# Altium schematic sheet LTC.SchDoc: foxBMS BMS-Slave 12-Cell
size A3; DocumentNumber: 2; SheetNumber: 2; SheetTotal: 15; AUTHOR: Fraunhofer IISB foxBMS Team; SheetDescription: Primary LTC6813
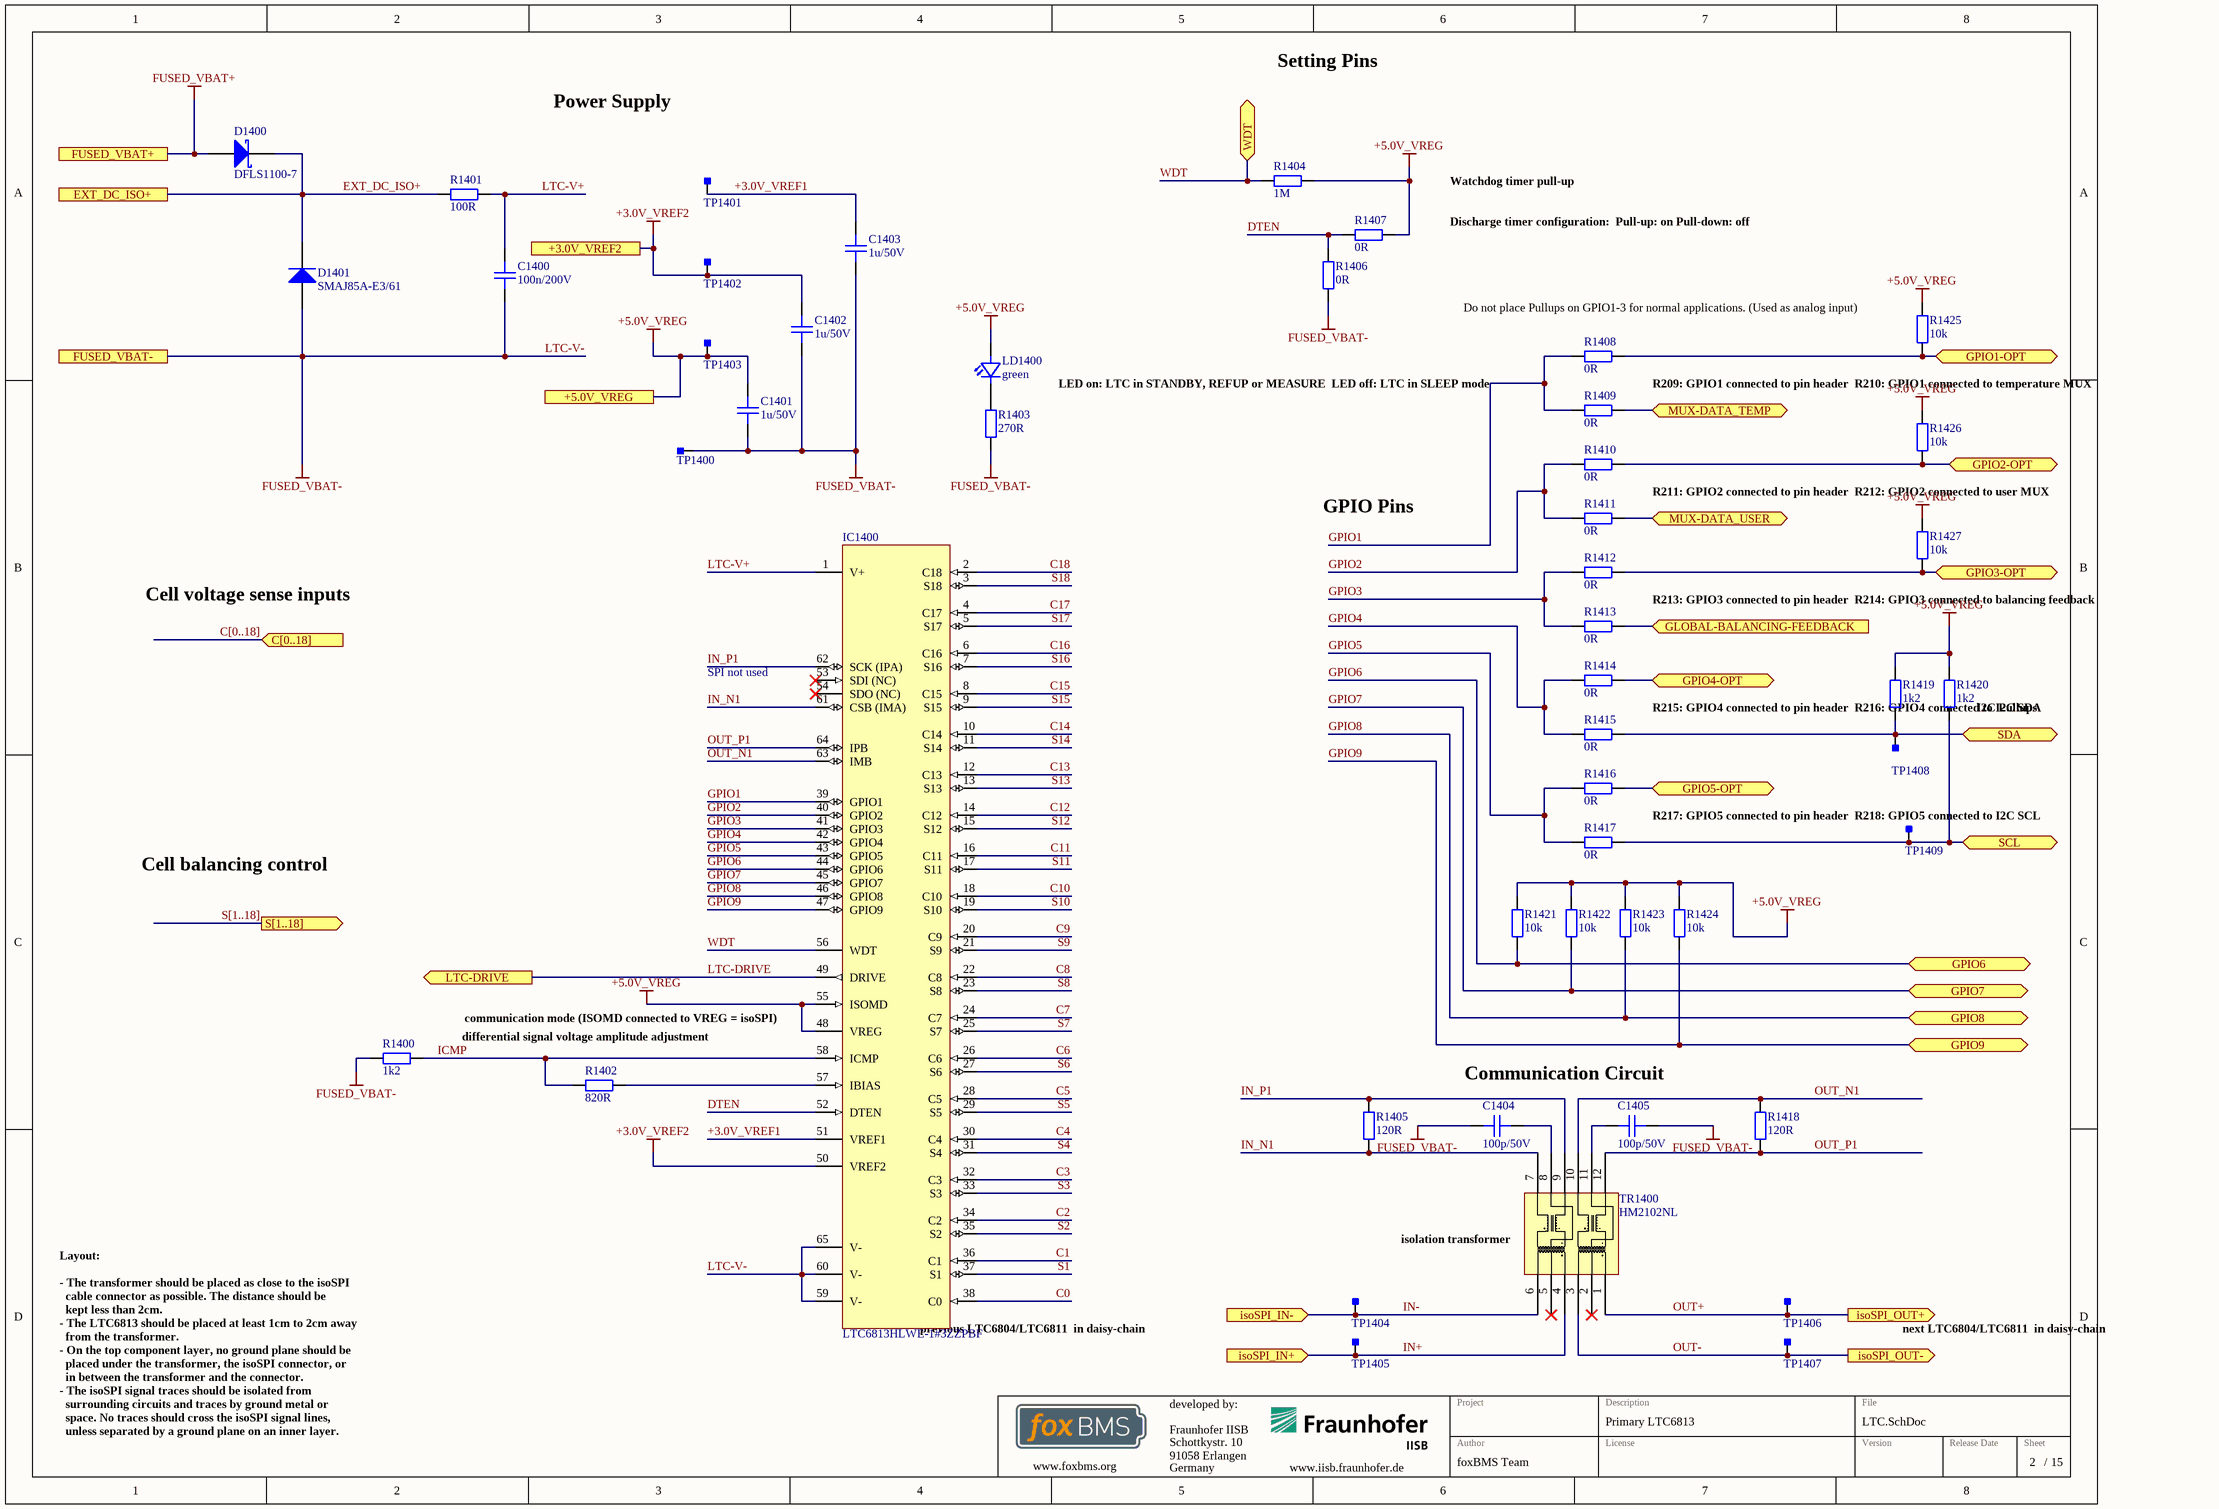
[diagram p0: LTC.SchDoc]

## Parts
C1400  100n/200V  [CAPC3216X18N]
C1401  1u/50V  [CAPC2012X14N]
C1402  1u/50V  [CAPC2012X14N]
C1403  1u/50V  [CAPC2012X14N]
C1404  100p/50V  [CAPC1608X08N]
C1405  100p/50V  [CAPC1608X08N]
D1400  DFLS1100-7  [DIOD-POWERDI123-2_V]
D1401  SMAJ85A-E3/61  [VISH-DO-214AC-2_L]
IC1400  LTC6813HLWE-1#3ZZPBF  [TSQFP50P1200X1200X160_HS-65N]
LD1400  green  [LEDC1608X07N]
R1400  1k2  [RESC1608X05N]
R1401  100R  [RESC2012X05N]
R1402  820R  [RESC1608X05N]
R1403  270R  [RESC1608X05N]
R1404  1M  [RESC1608X05N]
R1405  120R  [RESC1608X05N]
R1406  0R  [RESC1608X05N]
R1407  0R  [RESC1608X05N]
R1408  0R  [RESC1608X05N]
R1409  0R  [RESC1608X05N]
R1410  0R  [RESC1608X05N]
R1411  0R  [RESC1608X05N]
R1412  0R  [RESC1608X05N]
R1413  0R  [RESC1608X05N]
R1414  0R  [RESC1608X05N]
R1415  0R  [RESC1608X05N]
R1416  0R  [RESC1608X05N]
R1417  0R  [RESC1608X05N]
R1418  120R  [RESC1608X05N]
R1419  1k2  [RESC1608X05N]
R1420  1k2  [RESC1608X05N]
R1421  10k  [RESC1608X05N]
R1422  10k  [RESC1608X05N]
R1423  10k  [RESC1608X05N]
R1424  10k  [RESC1608X05N]
R1425  10k  [RESC1608X05N]
R1426  10k  [RESC1608X05N]
R1427  10k  [RESC1608X05N]
TP1400  Testpoint_Square  [Testpoint_S1]  (value not drawn)  (no BOM)
TP1401  Testpoint_Square  [Testpoint_S1]  (value not drawn)  (no BOM)
TP1402  Testpoint_Square  [Testpoint_S1]  (value not drawn)  (no BOM)
TP1403  Testpoint_Square  [Testpoint_S1]  (value not drawn)  (no BOM)
TP1404  Testpoint_Square  [Testpoint_S1]  (value not drawn)  (no BOM)
TP1405  Testpoint_Square  [Testpoint_S1]  (value not drawn)  (no BOM)
TP1406  Testpoint_Square  [Testpoint_S1]  (value not drawn)  (no BOM)
TP1407  Testpoint_Square  [Testpoint_S1]  (value not drawn)  (no BOM)
TP1408  Testpoint_Square  [Testpoint_S1]  (value not drawn)  (no BOM)
TP1409  Testpoint_Square  [Testpoint_S1]  (value not drawn)  (no BOM)
TR1400  HM2102NL  [HM2102NL]

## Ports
+3.0V_VREF2, +5.0V_VREG, C[0..18] (in), EXT_DC_ISO+, FUSED_VBAT+, FUSED_VBAT-, GLOBAL-BALANCING-FEEDBACK (in), GPIO1-OPT (bidir), GPIO2-OPT (bidir), GPIO3-OPT (bidir), GPIO4-OPT (bidir), GPIO5-OPT (bidir), GPIO6 (bidir), GPIO7 (bidir), GPIO8 (bidir), GPIO9 (bidir), isoSPI_IN+ (in), isoSPI_IN- (in), isoSPI_OUT+ (out), isoSPI_OUT- (out), LTC-DRIVE (out), MUX-DATA_TEMP (bidir), MUX-DATA_USER (bidir), S[1..18] (out), SCL (bidir), SDA (bidir), WDT (bidir)

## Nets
+3.0V_VREF2: C1402.2 IC1400.50(VREF2) TP1402.1 ; port +3.0V_VREF2
+5.0V_VREG: C1401.2 IC1400.48(VREG) IC1400.55(ISOMD) LD1400.2(A) R1404.2 R1407.2 R1419.2 R1420.2 R1421.2 R1422.2 R1423.2 R1424.2 R1425.2 R1426.2 R1427.2 TP1403.1 ; port +5.0V_VREG
FUSED_VBAT+: D1400.1(A) ; port FUSED_VBAT+
LTC-V-: C1400.2 C1401.1 C1402.1 C1403.1 C1404.1 C1405.1 D1401.2(A) IC1400.59(V-) IC1400.60(V-) IC1400.65(V-) R1400.1 R1403.1 R1406.1 TP1400.1 ; port FUSED_VBAT-  [also labelled FUSED_VBAT-]
+3.0V_VREF1: C1403.2 IC1400.51(VREF1) TP1401.1
C0: IC1400.38(C0)
C1: IC1400.36(C1)
C2: IC1400.34(C2)
C3: IC1400.32(C3)
C4: IC1400.30(C4)
C5: IC1400.28(C5)
C6: IC1400.26(C6)
C7: IC1400.24(C7)
C8: IC1400.22(C8)
C9: IC1400.20(C9)
C10: IC1400.18(C10)
C11: IC1400.16(C11)
C12: IC1400.14(C12)
C13: IC1400.12(C13)
C14: IC1400.10(C14)
C15: IC1400.8(C15)
C16: IC1400.6(C16)
C17: IC1400.4(C17)
C18: IC1400.2(C18)
DTEN: IC1400.52(DTEN) R1406.2 R1407.1
EXT_DC_ISO+: D1400.2(K) D1401.1(K) R1401.1 ; port EXT_DC_ISO+
GLOBAL-BALANCING-FEEDBACK: R1413.1 ; port GLOBAL-BALANCING-FEEDBACK
GPIO1: IC1400.39(GPIO1) R1408.2 R1409.2
GPIO1-OPT: R1408.1 R1425.1 ; port GPIO1-OPT
GPIO2: IC1400.40(GPIO2) R1410.2 R1411.2
GPIO2-OPT: R1410.1 R1426.1 ; port GPIO2-OPT
GPIO3: IC1400.41(GPIO3) R1412.2 R1413.2
GPIO3-OPT: R1412.1 R1427.1 ; port GPIO3-OPT
GPIO4: IC1400.42(GPIO4) R1414.2 R1415.2
GPIO4-OPT: R1414.1 ; port GPIO4-OPT
GPIO5: IC1400.43(GPIO5) R1416.2 R1417.2
GPIO5-OPT: R1416.1 ; port GPIO5-OPT
GPIO6: IC1400.44(GPIO6) R1421.1 ; port GPIO6
GPIO7: IC1400.45(GPIO7) R1422.1 ; port GPIO7
GPIO8: IC1400.46(GPIO8) R1423.1 ; port GPIO8
GPIO9: IC1400.47(GPIO9) R1424.1 ; port GPIO9
ICMP: IC1400.58(ICMP) R1400.2 R1402.1
IN+: TP1405.1 TR1400.4 ; port isoSPI_IN+
IN-: TP1404.1 TR1400.6 ; port isoSPI_IN-
IN_N1: IC1400.61(CSB_(IMA)) R1405.2 TR1400.7
IN_P1: IC1400.62(SCK_(IPA)) R1405.1 TR1400.9
LTC-DRIVE: IC1400.49(DRIVE) ; port LTC-DRIVE
LTC-V+: C1400.1 IC1400.1(V+) R1401.2
MUX-DATA_TEMP: R1409.1 ; port MUX-DATA_TEMP
MUX-DATA_USER: R1411.1 ; port MUX-DATA_USER
OUT+: TP1406.1 TR1400.1 ; port isoSPI_OUT+
OUT-: TP1407.1 TR1400.3 ; port isoSPI_OUT-
OUT_N1: IC1400.63(IMB) R1418.2 TR1400.10
OUT_P1: IC1400.64(IPB) R1418.1 TR1400.12
S1: IC1400.37(S1)
S2: IC1400.35(S2)
S3: IC1400.33(S3)
S4: IC1400.31(S4)
S5: IC1400.29(S5)
S6: IC1400.27(S6)
S7: IC1400.25(S7)
S8: IC1400.23(S8)
S9: IC1400.21(S9)
S10: IC1400.19(S10)
S11: IC1400.17(S11)
S12: IC1400.15(S12)
S13: IC1400.13(S13)
S14: IC1400.11(S14)
S15: IC1400.9(S15)
S16: IC1400.7(S16)
S17: IC1400.5(S17)
S18: IC1400.3(S18)
SCL: R1417.1 R1420.1 TP1409.1 ; port SCL
SDA: R1415.1 R1419.1 TP1408.1 ; port SDA
WDT: IC1400.56(WDT) R1404.1 ; port WDT
NetC1404_2: C1404.2 TR1400.8
NetC1405_2: C1405.2 TR1400.11
NetIC1400_57: IC1400.57(IBIAS) R1402.2
NetLD1400_1: LD1400.1(C) R1403.2

Not connected (* = marked no-connect by the designer): IC1400 53(SDI_(NC))* 54(SDO_(NC))*; TR1400 2* 5*

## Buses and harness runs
bus C[0..18] = port C[0..18]
bus S[1..18] = port S[1..18]

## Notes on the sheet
- Power Supply
- Setting Pins
- Watchdog timer pull-up
- Discharge timer configuration:
  Pull-up: on
  Pull-down: off
- (near R1425) Do not place Pullups on GPIO1-3 for normal applications. (Used as analog input)
- LED on: LTC in STANDBY, REFUP or MEASURE
  LED off: LTC in SLEEP mode
- R209: GPIO1 connected to pin header
  R210: GPIO1 connected to temperature MUX
- GPIO Pins
- R211: GPIO2 connected to pin header
  R212: GPIO2 connected to user MUX
- Cell voltage sense inputs
- R213: GPIO3 connected to pin header
  R214: GPIO3 connected to balancing feedback
- SPI not used
- R215: GPIO4 connected to pin header
  R216: GPIO4 connected to I2C SDA
- (near R1420) I2C Pullups
- (near TP1409) R217: GPIO5 connected to pin header
  R218: GPIO5 connected to I2C SCL
- Cell balancing control
- communication mode (ISOMD connected to VREG = isoSPI)
- differential signal voltage amplitude adjustment
- Communication Circuit
- (near TR1400) isolation transformer
- (near TP1405) previous LTC6804/LTC6811
  in daisy-chain
- next LTC6804/LTC6811
  in daisy-chain
- Layout:
  - The transformer should be placed as close to the isoSPI
  cable connector as possible. The distance should be
  kept less than 2cm.
  - The LTC6813 should be placed at least 1cm to 2cm away
  from the transformer.
  - On the top component layer, no ground plane should be
  placed under the transformer, the isoSPI connector, or
  in between the transformer and the connector.
  - The isoSPI signal traces should be isolated from
  surrounding circuits and traces by ground metal or
  space. No traces should cross the isoSPI signal lines,
  unless separated by a ground plane on an inner layer.

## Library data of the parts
C1400 = gen_C_ceramic_100n_200V_X7R_1206: MLCC; Capacitance: 100n; Rated Voltage: 200V; Dielectric: X7R; Case EIA: 1206; Case Metric: 3216; Automotive Qualified: True
C1401-C1403 = gen_C_ceramic_1u_50V_X7R_0805: MLCC; Capacitance: 1u; Rated Voltage: 50V; Dielectric: X7R; Case EIA: 0805; Case Metric: 2012; Automotive Qualified: True; Tolerance: ± 10%; AVT Set: x
C1404 C1405 = gen_C_ceramic_100p_50V_C0G_0603: MLCC; Capacitance: 100p; Rated Voltage: 50V; Dielectric: C0G; Case EIA: 0603; Case Metric: 1608; Automotive Qualified: True; Tolerance: ± 10%
D1400 = CMP-2000-05099-1: 1 A High Voltage Schottky Barrier Rectifier, 0.62 V, -55 to 175 degC, 2- Pin POWERDI123, Pb-Free, Tape and Reel; Manufacturer: Diodes Inc; Average Rectified Current-Max: 1A; Peak Current-Max: 40A; Forward Voltage: 0.77V; Reverse Current-Max: 1µA; Reverse Voltage-Max [Vrrm]: 100V
D1401 = CMP-0548-00243-2: Transient Voltage Suppressor, 6.40 to 231 V, 85 V Stand-off Voltage, Uni-Directional, -55 to 155 degC, 2-pin DO-214AC, Pb-Free, Tape and Reel; Manufacturer: Vishay Semiconductor; VWM (V): 85; PPPM (W): 400, 300; VBR Uni-Directional (V): 6.4 to 231; IFSM: 40 A; ID (uA): 1
IC1400 = LTC6813HLWE-1#3ZZPBF: 18 Cell Multicell Battery Monitor, -40 to 125 degC, Pb-Free; PartNumber: LTC6811HG-1#PBF; Manufacturer: Linear Technology; Type of Charger: Battery Stack Monitor; Vin Max(V): 60; Battery Chemistry: Li-Ion, Li-Polymer, NiMH; Number of Cells: > 1000 V of stacked Li-Ion cells; Automotive Qualified: True; PnP Package: QFP-64
LD1400 = LED_0603_green_AECQ: TLMG1100-GS08; Manufacturer: Vishay; Breakdown Voltage: 5V; Continuous Forward Current: 20mA; Forward Voltage @ 20mA: 2.1V; Automotive Qualified: True
R1400 R1419 R1420 = gen_R_1k2_0603: SMD Resistor 1k2 0603; Tolerance: 1%; Power: 0.1W; Case EIA: 0603; Case Metric: 1608; Maximum Working Voltage: 75V; PnP Package: R_0603; Automotive Qualified: True
R1401 = gen_R_100R_0805: SMD Resistor 100R 0805; Tolerance: 1%; Power: 0.125W; Case EIA: 0805; Case Metric: 2012; Maximum Working Voltage: 150V; PnP Package: R_0805; Automotive Qualified: True
R1402 = gen_R_820R_0603: SMD Resistor 820R 0603; Tolerance: 1%; Power: 0.1W; Case EIA: 0603; Case Metric: 1608; Maximum Working Voltage: 75V; PnP Package: R_0603; Automotive Qualified: True
R1403 = gen_R_270R_0603: SMD Resistor 270R 0603; Tolerance: 1%; Power: 0.1W; Case EIA: 0603; Case Metric: 1608; Maximum Working Voltage: 75V; PnP Package: R_0603; Automotive Qualified: True
R1404 = gen_R_1M_0603: SMD Resistor 1M 0603; Tolerance: 1%; Power: 0.1W; Case EIA: 0603; Case Metric: 1608; Maximum Working Voltage: 75V; PnP Package: R_0603; Automotive Qualified: True
R1405 R1418 = gen_R_120R_0603: SMD Resistor 120R 0603; Tolerance: 1%; Power: 0.1W; Case EIA: 0603; Case Metric: 1608; Maximum Working Voltage: 75V; PnP Package: R_0603; Automotive Qualified: True
R1406-R1417 = gen_R_0R_0603: SMD Resistor 0R 0603; Power: 0.1W; Case EIA: 0603; Case Metric: 1608; Maximum Working Voltage: 75V; PnP Package: R_0603; Automotive Qualified: True
R1421-R1427 = gen_R_10k_0603: SMD Resistor 10k 0603; Tolerance: 1%; Power: 0.1W; Case EIA: 0603; Case Metric: 1608; Maximum Working Voltage: 75V; PnP Package: R_0603; Automotive Qualified: True
TP1400-TP1409 = Testpoint_Square: Testpoint, square
TR1400 = HM2102NL: Pulse HM2102NL BMS Transformer; Automotive Qualified: True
